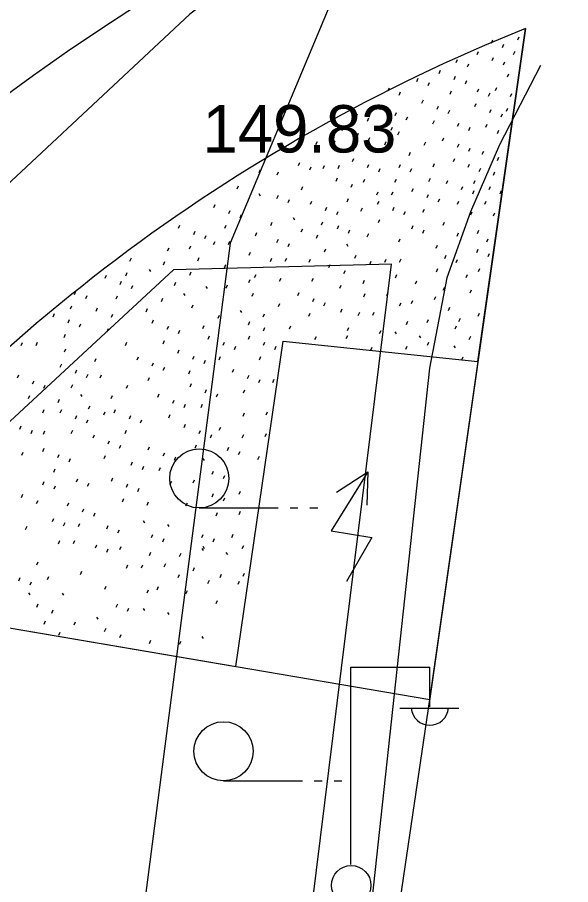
# Model space of a CAD drawing. Extents: x 419677 to 421689, y 4450851 to 4452923.
# Drawn here: x 420214.67 to 420228.69, y 4451942.32 to 4451964.28 of the extents above; entities that cross this region are included whole.
import ezdxf

# ---------------------------------------------------------------- set-up
doc = ezdxf.new("R2010")
doc.units = 0
for name, color, linetype in [('_TASARIM', 7, 'Continuous'), ('AA_HH', 7, 'Continuous'), ('AA_TARAMA-TİCARET', 7, 'Continuous'), ('AA_TRAFO_ALANI', 7, 'Continuous'), ('AA_YEŞİL_ALAN', 7, 'Continuous'), ('Level 15', 7, 'Continuous'), ('Level 62', 7, 'Continuous')]:
    doc.layers.add(name, color=color, linetype=linetype)

msp = doc.modelspace()

# ---------------------------------------------------------------- linework, layer by layer
at = {"layer": '_TASARIM'}
msp.add_arc((420243.944, 4451922.242), 55, 115.4775, 134.3905, dxfattribs=at)
at = {"layer": 'AA_HH'}
for p, q in [((420219.276, 4451951.86), (420221.276, 4451951.86)), ((420221.576, 4451951.86), (420221.776, 4451951.86)), ((420222.076, 4451951.86), (420222.276, 4451951.86)), ((420223.116, 4451942.829), (420223.116, 4451947.829)), ((420223.116, 4451947.829), (420225.116, 4451947.829)), ((420225.116, 4451946.829), (420225.116, 4451947.829)), ((420224.356, 4451946.789), (420225.856, 4451946.789)), ((420219.891, 4451944.949), (420221.891, 4451944.949)), ((420222.191, 4451944.949), (420222.391, 4451944.949)), ((420222.691, 4451944.949), (420222.891, 4451944.949))]:
    msp.add_line(p, q, dxfattribs=at)
for points in [[(420234.596, 4451973.43), (420228.639, 4451970.8), (420223.376, 4451967.647), (420219.033, 4451964.362), (420211.265, 4451957.117), (420208.13, 4451953.689)], [(420234.596, 4451973.43), (420228.639, 4451970.8), (420223.376, 4451967.647), (420219.033, 4451964.362), (420211.265, 4451957.117), (420208.13, 4451953.689)], [(420227.919, 4451963.066), (420226.886, 4451961.056), (420226.145, 4451959.356), (420225.546, 4451957.691), (420225.106, 4451955.399), (420223.165, 4451937.486), (420220.409, 4451915.127), (420216.884, 4451897.25), (420215.979, 4451890.718)], [(420222.136, 4451941.803), (420224.143, 4451958.03), (420218.619, 4451957.886), (420211.831, 4451951.612), (420208.064, 4451947.397)]]:
    msp.add_lwpolyline(points, dxfattribs=at)
for centre, radius in [((420219.276, 4451952.61), 0.75), ((420219.891, 4451945.699), 0.75), ((420223.126, 4451942.305), 0.5)]:
    msp.add_circle(centre, radius, dxfattribs=at)
msp.add_arc((420225.116, 4451946.833), 0.474, 184.8384, 355.1464, dxfattribs=at)
at = {"layer": 'AA_TARAMA-TİCARET'}
msp.add_line((420208.7, 4451949.803), (420225.114, 4451947.01), dxfattribs=at)
msp.add_lwpolyline([(420225.113, 4451947.01), (420220.409, 4451915.127), (420215.302, 4451882.018)], dxfattribs=at)
at = {"layer": 'AA_TRAFO_ALANI'}
for points in [[(420220.2, 4451947.846), (420221.402, 4451956.082), (420226.336, 4451955.566), (420225.113, 4451947.01)], [(420223.544, 4451952.775), (420222.619, 4451951.284), (420223.648, 4451951.112), (420223.005, 4451949.996)], [(420222.754, 4451952.261), (420223.544, 4451952.774), (420223.518, 4451951.932)]]:
    msp.add_lwpolyline(points, dxfattribs=at)
at = {"layer": 'AA_YEŞİL_ALAN'}
for p, q in [((420227.345, 4451963.714), (420227.38, 4451963.794)), ((420226.676, 4451963.63), (420226.712, 4451963.71)), ((420226.961, 4451963.523), (420226.996, 4451963.603)), ((420226.316, 4451963.341), (420226.351, 4451963.421)), ((420227.241, 4451963.345), (420227.277, 4451963.425)), ((420225.787, 4451963.137), (420225.822, 4451963.217)), ((420226.071, 4451963.03), (420226.107, 4451963.11)), ((420226.698, 4451963.187), (420226.734, 4451963.267)), ((420226.983, 4451963.08), (420227.018, 4451963.16)), ((420225.354, 4451962.865), (420225.389, 4451962.945)), ((420227.088, 4451962.777), (420227.123, 4451962.857)), ((420224.789, 4451962.661), (420224.825, 4451962.741)), ((420225.074, 4451962.554), (420225.11, 4451962.634)), ((420225.736, 4451962.711), (420225.772, 4451962.791)), ((420226.021, 4451962.604), (420226.056, 4451962.684)), ((420224.056, 4451962.42), (420224.092, 4451962.5)), ((420224.341, 4451962.314), (420224.376, 4451962.394)), ((420225.633, 4451962.342), (420225.668, 4451962.422)), ((420226.323, 4451962.397), (420226.359, 4451962.477)), ((420226.782, 4451962.43), (420226.817, 4451962.51)), ((420224.918, 4451962.111), (420224.954, 4451962.191)), ((420226.608, 4451962.29), (420226.644, 4451962.37)), ((420227.164, 4451962.276), (420227.199, 4451962.356)), ((420223.855, 4451961.949), (420223.891, 4451962.029)), ((420225.301, 4451961.957), (420225.336, 4451962.037)), ((420226.255, 4451962.025), (420226.291, 4451962.105)), ((420227.061, 4451961.907), (420227.096, 4451961.987)), ((420223.25, 4451961.764), (420223.286, 4451961.844)), ((420223.535, 4451961.658), (420223.57, 4451961.738)), ((420224.237, 4451961.795), (420224.273, 4451961.875)), ((420224.522, 4451961.688), (420224.558, 4451961.768)), ((420225.585, 4451961.85), (420225.621, 4451961.93)), ((420226.637, 4451961.871), (420226.673, 4451961.951)), ((420226.922, 4451961.764), (420226.958, 4451961.844)), ((420225.197, 4451961.588), (420225.233, 4451961.668)), ((420225.822, 4451961.526), (420225.858, 4451961.606)), ((420226.534, 4451961.502), (420226.57, 4451961.582)), ((420222.893, 4451961.422), (420222.929, 4451961.502)), ((420223.275, 4451961.268), (420223.311, 4451961.348)), ((420224.134, 4451961.426), (420224.17, 4451961.506)), ((420224.311, 4451961.311), (420224.346, 4451961.391)), ((420226.107, 4451961.42), (420226.142, 4451961.5)), ((420226.832, 4451961.346), (420226.868, 4451961.426)), ((420222.233, 4451961.063), (420222.269, 4451961.143)), ((420222.683, 4451961.076), (420222.719, 4451961.156)), ((420223.56, 4451961.161), (420223.596, 4451961.241)), ((420223.979, 4451961.056), (420224.015, 4451961.136)), ((420224.978, 4451961.05), (420225.013, 4451961.13)), ((420225.44, 4451961.154), (420225.475, 4451961.234)), ((420225.822, 4451961), (420225.858, 4451961.08)), ((420221.524, 4451960.871), (420221.56, 4451960.951)), ((420223.172, 4451960.899), (420223.208, 4451960.979)), ((420224.59, 4451960.788), (420224.625, 4451960.868)), ((420226.107, 4451960.893), (420226.142, 4451960.973)), ((420226.447, 4451960.815), (420226.483, 4451960.895)), ((420223.157, 4451960.632), (420223.192, 4451960.712)), ((420225.719, 4451960.631), (420225.754, 4451960.711)), ((420226.83, 4451960.661), (420226.865, 4451960.741)), ((420220.795, 4451960.354), (420220.831, 4451960.434)), ((420221.792, 4451960.529), (420221.827, 4451960.609)), ((420222.077, 4451960.422), (420222.112, 4451960.502)), ((420222.414, 4451960.454), (420222.45, 4451960.534)), ((420222.793, 4451960.457), (420222.829, 4451960.537)), ((420223.539, 4451960.478), (420223.574, 4451960.558)), ((420223.823, 4451960.372), (420223.859, 4451960.452)), ((420224.339, 4451960.478), (420224.374, 4451960.558)), ((420224.623, 4451960.372), (420224.659, 4451960.452)), ((420225.199, 4451960.499), (420225.235, 4451960.579)), ((420226.085, 4451960.489), (420226.121, 4451960.569)), ((420226.37, 4451960.382), (420226.406, 4451960.462)), ((420221.249, 4451960.292), (420221.285, 4451960.372)), ((420222.741, 4451960.136), (420222.777, 4451960.216)), ((420225.096, 4451960.129), (420225.132, 4451960.209)), ((420226.727, 4451960.291), (420226.762, 4451960.371)), ((420220.238, 4451959.939), (420220.274, 4451960.019)), ((420221.866, 4451959.918), (420221.902, 4451959.998)), ((420223.124, 4451959.982), (420223.159, 4451960.062)), ((420223.436, 4451960.109), (420223.471, 4451960.189)), ((420224.235, 4451960.109), (420224.271, 4451960.189)), ((420225.536, 4451960.076), (420225.572, 4451960.156)), ((420225.918, 4451959.921), (420225.954, 4451960.001)), ((420226.235, 4451960.076), (420226.27, 4451960.156)), ((420226.617, 4451959.921), (420226.653, 4451960.001)), ((420220.782, 4451959.821), (420220.817, 4451959.768)), ((420221.245, 4451959.699), (420221.281, 4451959.779)), ((420223.771, 4451959.786), (420223.807, 4451959.866)), ((420224.149, 4451959.789), (420224.185, 4451959.869)), ((420224.665, 4451959.873), (420224.701, 4451959.953)), ((420225.048, 4451959.719), (420225.083, 4451959.799)), ((420226.203, 4451959.815), (420226.239, 4451959.895)), ((420226.902, 4451959.815), (420226.937, 4451959.895)), ((420219.643, 4451959.468), (420219.678, 4451959.548)), ((420221.53, 4451959.592), (420221.565, 4451959.672)), ((420222.093, 4451959.549), (420222.129, 4451959.629)), ((420223.02, 4451959.613), (420223.056, 4451959.693)), ((420223.794, 4451959.549), (420223.83, 4451959.629)), ((420225.332, 4451959.612), (420225.368, 4451959.692)), ((420225.815, 4451959.552), (420225.851, 4451959.632)), ((420226.514, 4451959.552), (420226.549, 4451959.632)), ((420220.025, 4451959.314), (420220.06, 4451959.394)), ((420222.475, 4451959.395), (420222.511, 4451959.475)), ((420222.76, 4451959.288), (420222.796, 4451959.368)), ((420223.373, 4451959.376), (420223.409, 4451959.456)), ((420224.177, 4451959.395), (420224.212, 4451959.475)), ((420224.461, 4451959.288), (420224.497, 4451959.368)), ((420224.944, 4451959.35), (420224.98, 4451959.43)), ((420226.155, 4451959.279), (420226.19, 4451959.359)), ((420226.727, 4451959.256), (420226.763, 4451959.336)), ((420220.31, 4451959.207), (420220.345, 4451959.287)), ((420221.651, 4451959.213), (420221.687, 4451959.16)), ((420222.372, 4451959.026), (420222.408, 4451959.106)), ((420223.818, 4451959.086), (420223.854, 4451959.166)), ((420218.752, 4451958.941), (420218.787, 4451959.021)), ((420219.922, 4451958.945), (420219.957, 4451959.025)), ((420221.089, 4451959.015), (420221.125, 4451959.095)), ((420221.86, 4451958.85), (420221.896, 4451958.93)), ((420222.774, 4451958.929), (420222.81, 4451959.009)), ((420223.059, 4451958.822), (420223.094, 4451958.902)), ((420224.658, 4451958.929), (420224.693, 4451959.009)), ((420224.942, 4451958.822), (420224.978, 4451958.902)), ((420225.456, 4451959.018), (420225.492, 4451959.098)), ((420226.326, 4451958.811), (420226.362, 4451958.891)), ((420219.134, 4451958.787), (420219.169, 4451958.867)), ((420219.419, 4451958.681), (420219.454, 4451958.761)), ((420220.701, 4451958.752), (420220.737, 4451958.832)), ((420221.245, 4451958.585), (420221.281, 4451958.665)), ((420222.243, 4451958.696), (420222.278, 4451958.776)), ((420223.534, 4451958.727), (420223.569, 4451958.807)), ((420224.334, 4451958.595), (420224.369, 4451958.675)), ((420225.81, 4451958.745), (420225.845, 4451958.825)), ((420226.563, 4451958.596), (420226.598, 4451958.676)), ((420218.475, 4451958.368), (420218.511, 4451958.448)), ((420219.031, 4451958.418), (420219.066, 4451958.498)), ((420219.639, 4451958.53), (420219.675, 4451958.61)), ((420220.018, 4451958.533), (420220.054, 4451958.613)), ((420221.53, 4451958.478), (420221.565, 4451958.558)), ((420223.008, 4451958.545), (420223.043, 4451958.491)), ((420225.274, 4451958.436), (420225.31, 4451958.516)), ((420220.541, 4451958.258), (420220.577, 4451958.338)), ((420222.446, 4451958.346), (420222.482, 4451958.426)), ((420223.217, 4451958.182), (420223.253, 4451958.262)), ((420225.498, 4451958.18), (420225.534, 4451958.26)), ((420226.308, 4451958.332), (420226.344, 4451958.412)), ((420226.593, 4451958.225), (420226.628, 4451958.305)), ((420217.52, 4451958.111), (420217.555, 4451958.191)), ((420218.367, 4451958.02), (420218.402, 4451958.1)), ((420219.241, 4451958.121), (420219.277, 4451958.201)), ((420219.913, 4451957.943), (420219.949, 4451958.023)), ((420221.077, 4451958.105), (420221.113, 4451958.185)), ((420221.456, 4451958.108), (420221.492, 4451958.188)), ((420222.058, 4451958.084), (420222.094, 4451958.164)), ((420222.559, 4451957.949), (420222.595, 4451958.029)), ((420223.599, 4451958.028), (420223.635, 4451958.108)), ((420223.975, 4451958.083), (420224.011, 4451958.163)), ((420224.353, 4451958.086), (420224.389, 4451958.166)), ((420225.783, 4451958.073), (420225.818, 4451958.153)), ((420217.417, 4451957.742), (420217.452, 4451957.822)), ((420218.007, 4451957.897), (420218.043, 4451957.844)), ((420219.034, 4451957.759), (420219.069, 4451957.839)), ((420222.941, 4451957.795), (420222.977, 4451957.875)), ((420225.287, 4451957.843), (420225.322, 4451957.923)), ((420226.35, 4451957.846), (420226.386, 4451957.926)), ((420216.888, 4451957.676), (420216.924, 4451957.756)), ((420217.271, 4451957.522), (420217.306, 4451957.602)), ((420218.646, 4451957.497), (420218.681, 4451957.577)), ((420220.529, 4451957.568), (420220.565, 4451957.648)), ((420220.679, 4451957.695), (420220.715, 4451957.775)), ((420221.311, 4451957.6), (420221.347, 4451957.68)), ((420222.131, 4451957.6), (420222.167, 4451957.68)), ((420223.427, 4451957.547), (420223.463, 4451957.627)), ((420224.248, 4451957.691), (420224.284, 4451957.771)), ((420224.751, 4451957.535), (420224.787, 4451957.615)), ((420226.04, 4451957.695), (420226.075, 4451957.775)), ((420216.116, 4451957.268), (420216.152, 4451957.348)), ((420217.555, 4451957.415), (420217.591, 4451957.495)), ((420219.445, 4451957.472), (420219.48, 4451957.418)), ((420219.954, 4451957.428), (420219.99, 4451957.508)), ((420222.838, 4451957.426), (420222.874, 4451957.506)), ((420225.458, 4451957.375), (420225.494, 4451957.455)), ((420226.141, 4451957.306), (420226.177, 4451957.386)), ((420216.401, 4451957.162), (420216.437, 4451957.242)), ((420217.167, 4451957.152), (420217.203, 4451957.232)), ((420218.315, 4451957.091), (420218.35, 4451957.171)), ((420218.876, 4451957.289), (420218.912, 4451957.236)), ((420220.615, 4451957.22), (420220.65, 4451957.3)), ((420221.769, 4451957.24), (420221.805, 4451957.32)), ((420222.151, 4451957.086), (420222.187, 4451957.166)), ((420223.445, 4451957.209), (420223.481, 4451957.289)), ((420224.024, 4451957.24), (420224.06, 4451957.32)), ((420225.234, 4451957.138), (420225.269, 4451957.218)), ((420216.013, 4451956.899), (420216.049, 4451956.979)), ((420216.666, 4451956.845), (420216.701, 4451956.925)), ((420217.927, 4451956.828), (420217.962, 4451956.908)), ((420219.086, 4451956.926), (420219.121, 4451957.006)), ((420221.282, 4451956.959), (420221.317, 4451957.039)), ((420222.436, 4451956.979), (420222.472, 4451957.059)), ((420224.352, 4451956.975), (420224.388, 4451957.055)), ((420224.652, 4451957.035), (420224.687, 4451957.115)), ((420225.587, 4451956.864), (420225.623, 4451956.944)), ((420215.572, 4451956.704), (420215.608, 4451956.784)), ((420217.048, 4451956.691), (420217.083, 4451956.771)), ((420219.753, 4451956.665), (420219.788, 4451956.745)), ((420220.314, 4451956.864), (420220.35, 4451956.81)), ((420220.894, 4451956.697), (420220.929, 4451956.777)), ((420222.048, 4451956.717), (420222.084, 4451956.797)), ((420222.861, 4451956.819), (420222.896, 4451956.899)), ((420223.306, 4451956.738), (420223.342, 4451956.818)), ((420223.673, 4451956.742), (420223.709, 4451956.822)), ((420226.34, 4451956.716), (420226.376, 4451956.796)), ((420215.954, 4451956.549), (420215.99, 4451956.629)), ((420216.239, 4451956.443), (420216.275, 4451956.523)), ((420218.083, 4451956.542), (420218.119, 4451956.622)), ((420218.466, 4451956.387), (420218.501, 4451956.467)), ((420219.365, 4451956.403), (420219.4, 4451956.483)), ((420220.524, 4451956.501), (420220.559, 4451956.581)), ((420221.564, 4451956.395), (420221.6, 4451956.475)), ((420224.523, 4451956.507), (420224.559, 4451956.587)), ((420225.051, 4451956.556), (420225.087, 4451956.636)), ((420225.759, 4451956.396), (420225.795, 4451956.476)), ((420225.856, 4451956.586), (420225.891, 4451956.666)), ((420215.851, 4451956.18), (420215.887, 4451956.26)), ((420216.945, 4451956.322), (420216.98, 4451956.402)), ((420218.75, 4451956.281), (420218.786, 4451956.361)), ((420220.906, 4451956.347), (420220.941, 4451956.427)), ((420223.032, 4451956.352), (420223.068, 4451956.432)), ((420223.845, 4451956.274), (420223.881, 4451956.354)), ((420224.232, 4451956.32), (420224.268, 4451956.267)), ((420214.764, 4451955.974), (420214.8, 4451956.054)), ((420215.143, 4451955.977), (420215.179, 4451956.057)), ((420217.405, 4451955.977), (420217.441, 4451956.057)), ((420218.362, 4451956.018), (420218.398, 4451956.098)), ((420219.501, 4451956.136), (420219.536, 4451956.216)), ((420219.883, 4451955.982), (420219.919, 4451956.062)), ((420220.524, 4451956.136), (420220.559, 4451956.216)), ((420220.906, 4451955.982), (420220.941, 4451956.062)), ((420222.207, 4451956.125), (420222.242, 4451956.205)), ((420223, 4451956.148), (420223.036, 4451956.228)), ((420224.846, 4451956.221), (420224.881, 4451956.168)), ((420225.057, 4451955.982), (420225.092, 4451956.062)), ((420226.118, 4451956.13), (420226.153, 4451956.21)), ((420215.862, 4451955.813), (420215.898, 4451955.893)), ((420218.731, 4451955.782), (420218.767, 4451955.862)), ((420220.168, 4451955.876), (420220.203, 4451955.956)), ((420221.191, 4451955.876), (420221.226, 4451955.956)), ((420223.624, 4451955.854), (420223.66, 4451955.934)), ((420224.51, 4451955.88), (420224.546, 4451955.96)), ((420225.726, 4451955.965), (420225.762, 4451955.911)), ((420216.629, 4451955.565), (420216.665, 4451955.645)), ((420217.699, 4451955.61), (420217.734, 4451955.69)), ((420219.114, 4451955.628), (420219.149, 4451955.708)), ((420219.398, 4451955.521), (420219.434, 4451955.601)), ((420219.78, 4451955.613), (420219.816, 4451955.693)), ((420220.803, 4451955.613), (420220.838, 4451955.693)), ((420225.927, 4451955.61), (420225.963, 4451955.69)), ((420215.754, 4451955.428), (420215.79, 4451955.508)), ((420218.081, 4451955.456), (420218.116, 4451955.536)), ((420218.365, 4451955.349), (420218.401, 4451955.429)), ((420220.119, 4451955.296), (420220.154, 4451955.376)), ((420214.671, 4451955.154), (420214.706, 4451955.234)), ((420216.137, 4451955.274), (420216.172, 4451955.354)), ((420216.421, 4451955.167), (420216.457, 4451955.247)), ((420216.767, 4451955.154), (420216.802, 4451955.234)), ((420217.978, 4451955.087), (420218.013, 4451955.167)), ((420219.01, 4451955.259), (420219.046, 4451955.339)), ((420220.501, 4451955.142), (420220.536, 4451955.222)), ((420215.053, 4451955), (420215.089, 4451955.08)), ((420215.338, 4451954.893), (420215.373, 4451954.973)), ((420216.033, 4451954.904), (420216.069, 4451954.984)), ((420217.434, 4451954.893), (420217.469, 4451954.973)), ((420219.045, 4451954.931), (420219.081, 4451955.011)), ((420220.786, 4451955.035), (420220.821, 4451955.115)), ((420221.14, 4451955.039), (420221.175, 4451955.119)), ((420214.95, 4451954.631), (420214.985, 4451954.711)), ((420216.264, 4451954.733), (420216.299, 4451954.68)), ((420217.046, 4451954.631), (420217.081, 4451954.711)), ((420218.225, 4451954.668), (420218.261, 4451954.748)), ((420219.428, 4451954.777), (420219.463, 4451954.857)), ((420219.712, 4451954.671), (420219.748, 4451954.751)), ((420220.398, 4451954.773), (420220.433, 4451954.853)), ((420215.702, 4451954.535), (420215.738, 4451954.615)), ((420218.607, 4451954.514), (420218.643, 4451954.594)), ((420219.324, 4451954.408), (420219.36, 4451954.488)), ((420215.314, 4451954.272), (420215.35, 4451954.352)), ((420215.754, 4451954.273), (420215.79, 4451954.353)), ((420216.473, 4451954.37), (420216.509, 4451954.45)), ((420216.856, 4451954.216), (420216.891, 4451954.296)), ((420217.121, 4451954.273), (420217.157, 4451954.353)), ((420218.892, 4451954.407), (420218.928, 4451954.487)), ((420220.969, 4451954.217), (420221.004, 4451954.297)), ((420216.137, 4451954.119), (420216.172, 4451954.199)), ((420216.421, 4451954.012), (420216.457, 4451954.092)), ((420217.504, 4451954.119), (420217.539, 4451954.199)), ((420217.788, 4451954.012), (420217.824, 4451954.092)), ((420218.504, 4451954.145), (420218.54, 4451954.225)), ((420220.389, 4451954.186), (420220.425, 4451954.266)), ((420214.729, 4451953.856), (420214.765, 4451953.936)), ((420215.014, 4451953.749), (420215.049, 4451953.829)), ((420216.033, 4451953.75), (420216.069, 4451953.83)), ((420217.4, 4451953.75), (420217.436, 4451953.83)), ((420218.893, 4451953.899), (420218.929, 4451953.979)), ((420219.782, 4451953.829), (420219.818, 4451953.909)), ((420215.326, 4451953.73), (420215.362, 4451953.81)), ((420216.585, 4451953.635), (420216.62, 4451953.715)), ((420219.276, 4451953.745), (420219.311, 4451953.825)), ((420219.56, 4451953.638), (420219.596, 4451953.718)), ((420220.366, 4451953.638), (420220.402, 4451953.718)), ((420220.946, 4451953.67), (420220.981, 4451953.75)), ((420216.967, 4451953.481), (420217.002, 4451953.561)), ((420217.252, 4451953.374), (420217.287, 4451953.454)), ((420217.982, 4451953.332), (420218.018, 4451953.412)), ((420219.172, 4451953.375), (420219.208, 4451953.455)), ((420219.99, 4451953.319), (420220.025, 4451953.399)), ((420214.778, 4451953.194), (420214.813, 4451953.274)), ((420215.309, 4451953.291), (420215.344, 4451953.371)), ((420215.691, 4451953.137), (420215.727, 4451953.217)), ((420216.864, 4451953.112), (420216.899, 4451953.192)), ((420218.364, 4451953.178), (420218.4, 4451953.258)), ((420220.274, 4451953.212), (420220.31, 4451953.292)), ((420215.976, 4451953.03), (420216.011, 4451953.11)), ((420217.549, 4451952.945), (420217.585, 4451953.025)), ((420218.649, 4451953.071), (420218.685, 4451953.151)), ((420219.362, 4451953.115), (420219.398, 4451953.061)), ((420220.763, 4451953.088), (420220.799, 4451953.168)), ((420215.588, 4451952.768), (420215.623, 4451952.848)), ((420217.834, 4451952.838), (420217.869, 4451952.918)), ((420218.261, 4451952.808), (420218.297, 4451952.888)), ((420219.605, 4451952.712), (420219.64, 4451952.792)), ((420215.311, 4451952.448), (420215.347, 4451952.528)), ((420216.162, 4451952.519), (420216.197, 4451952.599)), ((420217.05, 4451952.542), (420217.086, 4451952.622)), ((420218.541, 4451952.463), (420218.577, 4451952.543)), ((420219.12, 4451952.494), (420219.156, 4451952.574)), ((420219.889, 4451952.605), (420219.925, 4451952.685)), ((420215.596, 4451952.342), (420215.632, 4451952.422)), ((420216.447, 4451952.412), (420216.482, 4451952.492)), ((420217.433, 4451952.388), (420217.468, 4451952.468)), ((420217.717, 4451952.281), (420217.753, 4451952.361)), ((420214.772, 4451952.127), (420214.808, 4451952.207)), ((420217.33, 4451952.018), (420217.365, 4451952.098)), ((420219.605, 4451952.145), (420219.64, 4451952.225)), ((420219.889, 4451952.038), (420219.925, 4451952.118)), ((420220.284, 4451952.209), (420220.32, 4451952.289)), ((420215.154, 4451951.973), (420215.19, 4451952.053)), ((420215.937, 4451951.914), (420215.972, 4451951.994)), ((420217.957, 4451951.935), (420217.992, 4451952.015)), ((420218.938, 4451951.912), (420218.974, 4451951.992)), ((420216.319, 4451951.76), (420216.354, 4451951.84)), ((420216.604, 4451951.653), (420216.639, 4451951.733)), ((420219.704, 4451951.665), (420219.74, 4451951.745)), ((420220.284, 4451951.696), (420220.32, 4451951.776)), ((420215.554, 4451951.517), (420215.59, 4451951.597)), ((420215.839, 4451951.41), (420215.875, 4451951.49)), ((420216.216, 4451951.391), (420216.251, 4451951.471)), ((420216.931, 4451951.335), (420216.967, 4451951.415)), ((420217.856, 4451951.54), (420217.892, 4451951.487)), ((420218.47, 4451951.441), (420218.506, 4451951.388)), ((420214.877, 4451951.319), (420214.913, 4451951.399)), ((420217.216, 4451951.228), (420217.252, 4451951.308)), ((420220.102, 4451951.114), (420220.138, 4451951.194)), ((420215.71, 4451950.956), (420215.746, 4451951.036)), ((420216.089, 4451950.959), (420216.125, 4451951.039)), ((420218.066, 4451951.112), (420218.101, 4451951.192)), ((420218.35, 4451951.005), (420218.386, 4451951.085)), ((420219.341, 4451951.112), (420219.377, 4451951.192)), ((420219.626, 4451951.005), (420219.662, 4451951.085)), ((420216.648, 4451950.849), (420216.683, 4451950.929)), ((420216.933, 4451950.742), (420216.968, 4451950.822)), ((420217.261, 4451950.806), (420217.296, 4451950.886)), ((420219.34, 4451950.833), (420219.375, 4451950.78)), ((420219.362, 4451950.889), (420219.398, 4451950.836)), ((420220.366, 4451950.832), (420220.402, 4451950.912)), ((420218.014, 4451950.657), (420218.049, 4451950.737)), ((420218.778, 4451950.635), (420218.813, 4451950.715)), ((420219.953, 4451950.734), (420219.989, 4451950.68)), ((420215.163, 4451950.419), (420215.198, 4451950.499)), ((420217.432, 4451950.338), (420217.468, 4451950.418)), ((420217.81, 4451950.341), (420217.846, 4451950.421)), ((420218.39, 4451950.372), (420218.426, 4451950.452)), ((420219.12, 4451950.269), (420219.156, 4451950.349)), ((420214.704, 4451950.018), (420214.739, 4451950.098)), ((420215.433, 4451950.049), (420215.468, 4451950.129)), ((420216.267, 4451950.176), (420216.303, 4451950.256)), ((420218.744, 4451950.098), (420218.779, 4451950.178)), ((420219.807, 4451950.101), (420219.843, 4451950.181)), ((420220.387, 4451950.133), (420220.422, 4451950.213)), ((420214.988, 4451949.911), (420215.024, 4451949.991)), ((420216.884, 4451949.802), (420216.92, 4451949.882)), ((420219.497, 4451949.95), (420219.532, 4451950.03)), ((420220.261, 4451949.927), (420220.297, 4451950.007)), ((420208.711, 4451949.801), (420225.114, 4451947.01)), ((420214.948, 4451949.715), (420214.983, 4451949.661)), ((420215.8, 4451949.705), (420215.835, 4451949.652)), ((420217.957, 4451949.71), (420217.992, 4451949.79)), ((420218.208, 4451949.79), (420218.244, 4451949.87)), ((420218.938, 4451949.687), (420218.974, 4451949.767)), ((420219.704, 4451949.439), (420219.74, 4451949.519)), ((420215.157, 4451949.352), (420215.192, 4451949.432)), ((420215.539, 4451949.198), (420215.575, 4451949.278)), ((420217.174, 4451949.35), (420217.21, 4451949.43)), ((420217.459, 4451949.243), (420217.495, 4451949.323)), ((420217.856, 4451949.315), (420217.892, 4451949.261)), ((420215.343, 4451948.922), (420215.378, 4451949.002)), ((420216.669, 4451949.097), (420216.705, 4451949.044)), ((420218.47, 4451949.216), (420218.506, 4451949.162)), ((420216.107, 4451948.899), (420216.143, 4451948.979)), ((420216.878, 4451948.734), (420216.914, 4451948.814)), ((420215.719, 4451948.636), (420215.755, 4451948.716)), ((420217.261, 4451948.58), (420217.296, 4451948.66)), ((420219.34, 4451948.608), (420219.375, 4451948.554)), ((420218.014, 4451948.432), (420218.049, 4451948.512)), ((420218.778, 4451948.409), (420218.813, 4451948.489))]:
    msp.add_line(p, q, dxfattribs=at)
for points in [[(420208.711, 4451949.801), (420220.2, 4451947.846), (420221.402, 4451956.082), (420226.336, 4451955.566), (420227.54, 4451963.997)], [(420227.54, 4451963.997), (420225.1, 4451946.914)]]:
    msp.add_lwpolyline(points, dxfattribs=at)
msp.add_arc((420244.27, 4451922.223), 45, 111.8254, 142.2044, dxfattribs=at)
at = {"layer": 'Level 15'}
msp.add_lwpolyline([(420414.132, 4451911.018), (420415.765, 4451915.419), (420282.101, 4451967.569), (420224.504, 4451969.178), (420220.055, 4451958.563), (420205.131, 4451843.779), (420215.712, 4451841.911), (420221.376, 4451877.395), (420222.223, 4451877.252)], dxfattribs=at)
at = {"layer": 'Level 62'}
msp.add_arc((420244.27, 4451922.223), 50, 86.5224, 164.9279, dxfattribs=at)
msp.add_open_spline([(420174.141, 4451957.431), (420207.126, 4451990.277), (420233.269, 4451982.965), (420233.274, 4451982.982)], degree=2, dxfattribs=at)

# ---------------------------------------------------------------- texts
at = {"layer": 'AA_HH'}
msp.add_text('149.83 ', height=1.2, rotation=359.9981, dxfattribs=at).set_placement((420219.362, 4451960.861))

doc.saveas('drawing.dxf')
